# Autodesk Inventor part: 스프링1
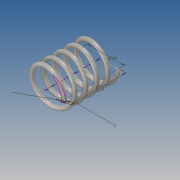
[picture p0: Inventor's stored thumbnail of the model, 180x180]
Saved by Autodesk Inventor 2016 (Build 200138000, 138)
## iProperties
Created: 2016-10
Part Number: 스프링1
Material: 강철, 탄소
Document SubType Name: Modeling
Designer: Administrator
Density: 7.85 g/cm^3
Appearance: 반연마
Mass: 6.86321 g
Surface Area: 17.7466 cm^2
Volume: 0.874294 cm^3
Author: Administrator
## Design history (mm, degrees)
sketch "스케치1"
  geometry: L1 (0, 0)-(-9, 0); L2 (-9, 0)-(-9, -27); L3 (-9, -27)-(0, -27); L4 (0, -27)-(0, 0); C1 r 1 at (-9, 0)
  constraints: 8 end point, 2 parallel, 1 centre point, 1 coincident, 1 horizontal, 1 perpendicular
  dimensions: "d0" = 2 diameter of C1; "d1" = 27 distance of L1.end L2.end (derived); "d2" = 18 diameter of L2 L4
feature "코일1" pitch "d3" = 10; turns "d5" = 5; dims "d4" = 27 (= d1), "d6" = 0, angle "d7" = 90 deg, angle "d8" = 90 deg, "d9" = 0, "d10" = 0
sketch "스케치2"
  geometry: L1 (10, 0)-(8, 0) reference; 1 further point
  constraints: 1 horizontal alignment
  node "절단 모서리 투영1"
extrude "돌출1" cut sketch "스케치2" stored distance "d11" = 10; taper "d12" = 0 deg
node "작업 평면3"
sketch "스케치3"
  geometry: L1 (-1, 0)-(1, 0) reference; 1 further point
  constraints: 1 horizontal alignment
extrude "돌출2" cut sketch "스케치3" stored distance "d14" = 0; taper "d15" = 0 deg
node "솔리드1"
node "절단 모서리 투영2"
other parameters: "d13" = 90 deg
